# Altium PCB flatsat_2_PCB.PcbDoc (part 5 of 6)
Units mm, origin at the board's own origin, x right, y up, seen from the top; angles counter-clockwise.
Board outline 400 x 250 mm, 4 copper layers (Top Layer, FlatSat GND, FlatSat VCC, Bottom Layer), stack 2.102 mm thick; 196 components, 289 nets, 1724 pads, 1139 vias.
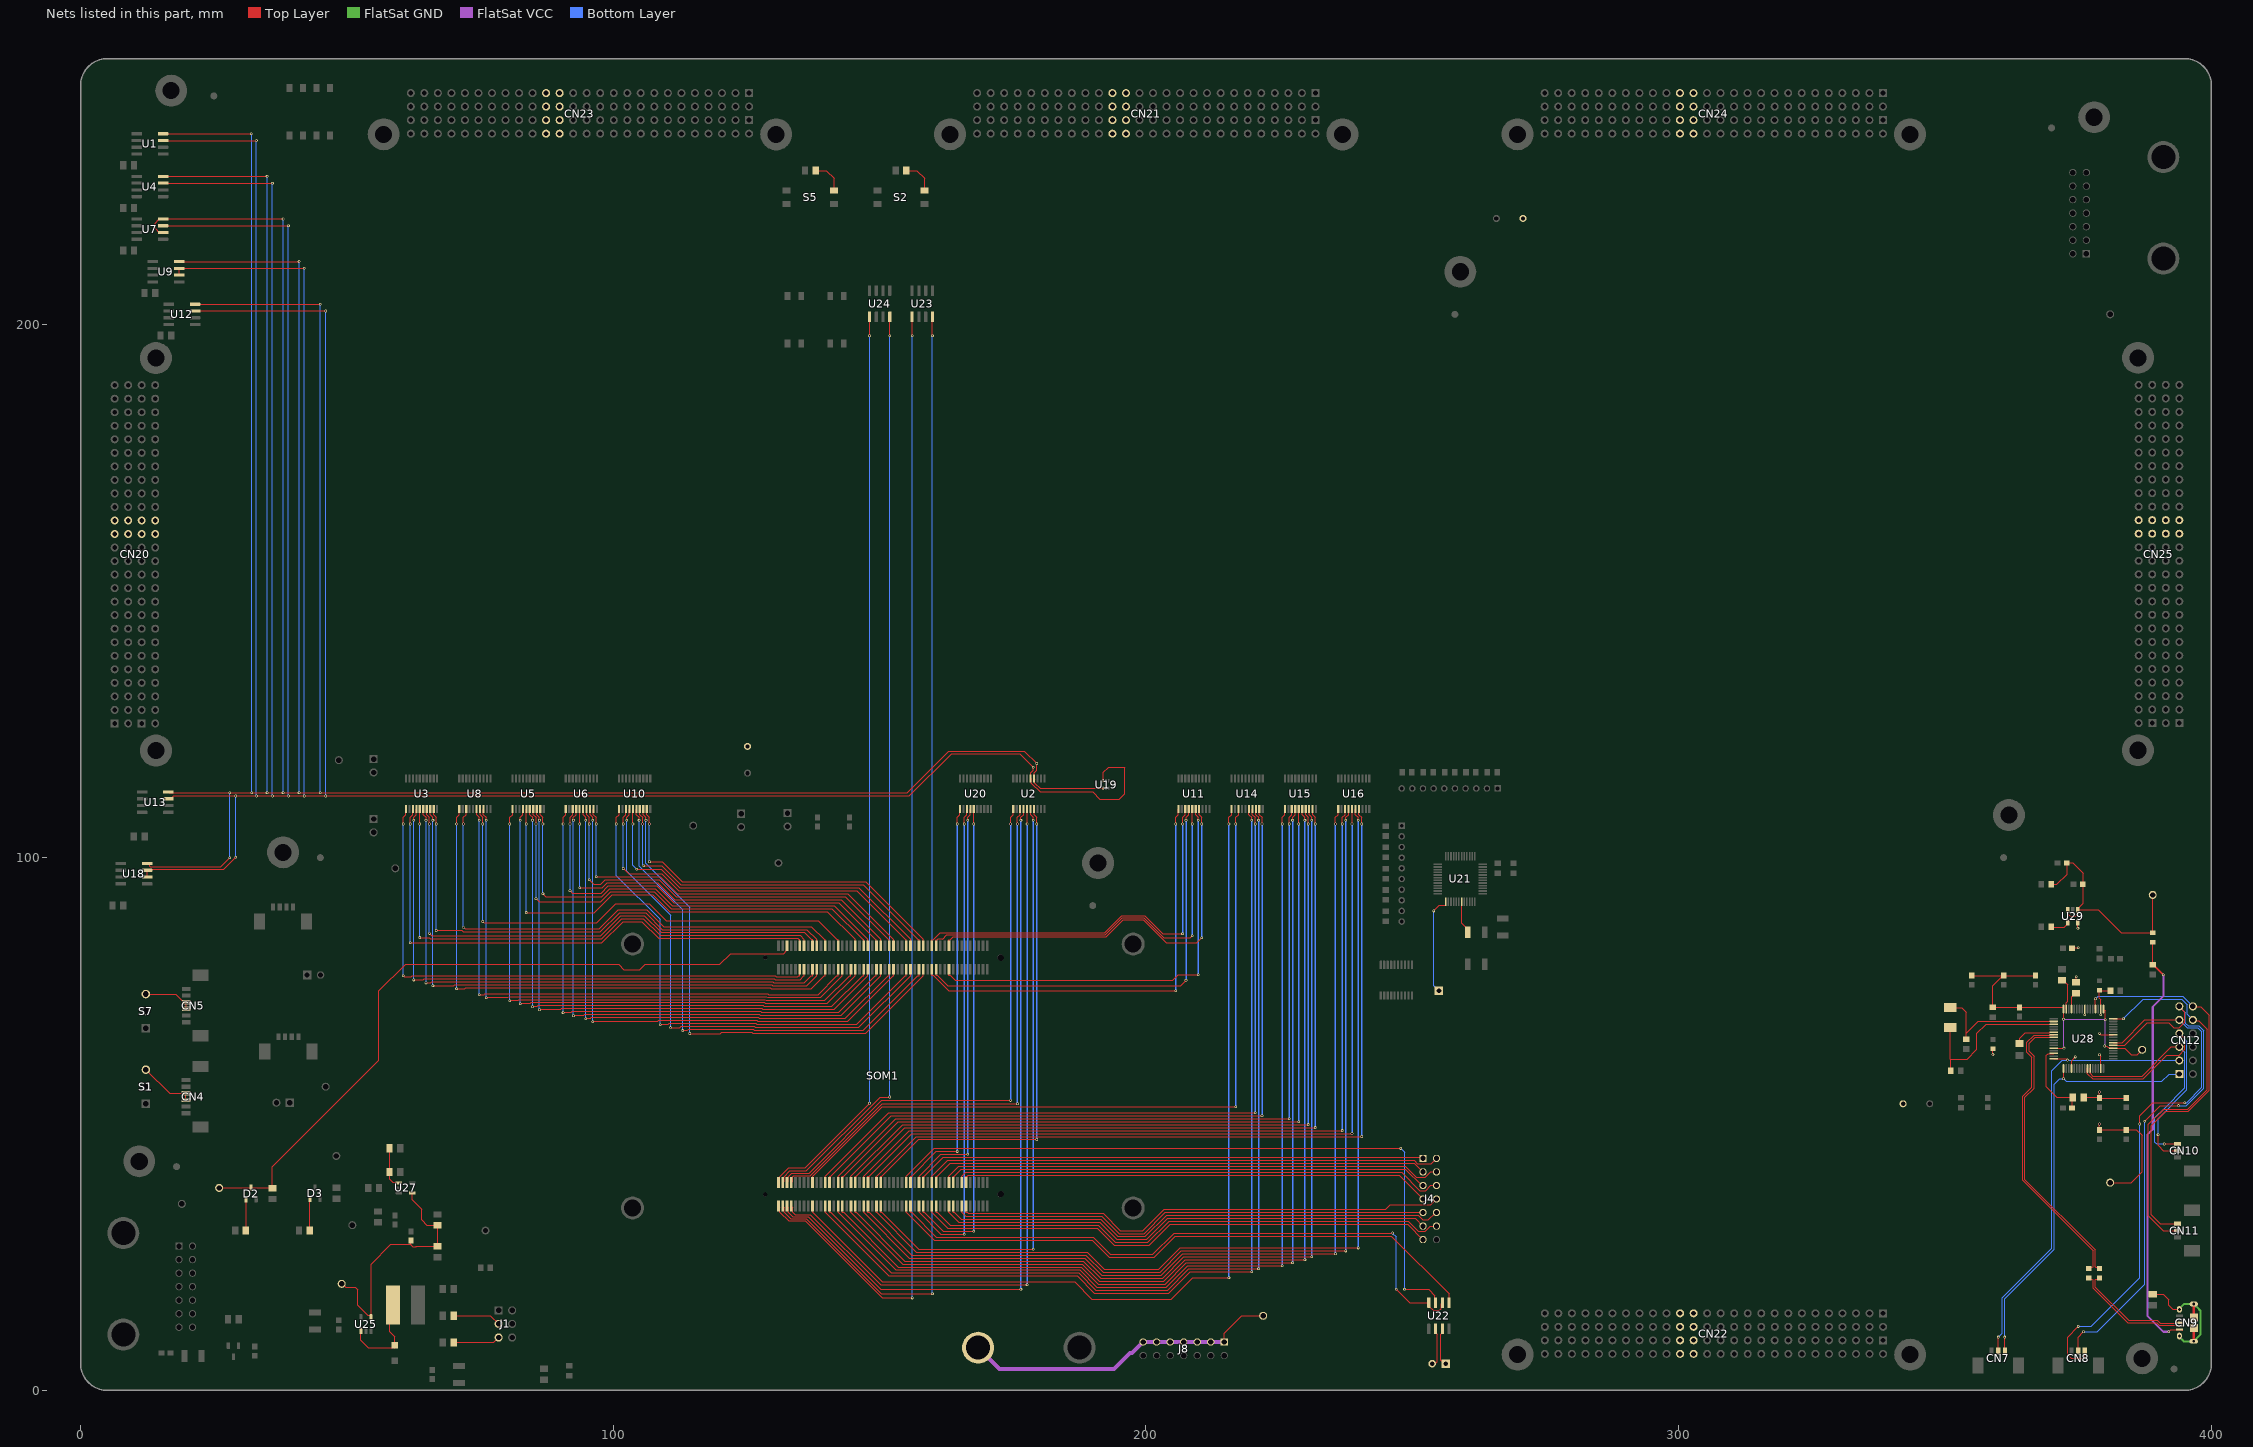
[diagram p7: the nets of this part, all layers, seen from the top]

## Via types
v1: diameter 0.508, hole 0.3, Top Layer to Bottom Layer, tented both sides, 1073 vias
v2: diameter 0.762, hole 0.45, Top Layer to Bottom Layer, tented both sides, 66 vias

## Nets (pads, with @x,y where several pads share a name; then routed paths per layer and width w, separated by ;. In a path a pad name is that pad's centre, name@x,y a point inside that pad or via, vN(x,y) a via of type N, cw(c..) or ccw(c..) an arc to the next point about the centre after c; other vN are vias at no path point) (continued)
NetC18_1: C18.1 U21.43 | length 6.2
  Top Layer w0.203: U21.43@259.25,91.75 259.25,87.7 260.4,86.55 C18.1@260.4,86
NetC31_1: C31.1 CN9.1 FB2.1 | length 80.2
  Top Layer w0.203: C31.1@389,79.925 FB2.1@389,84.111 ; v1(392,11) 392.4,11.4 CN9.1@394,11.4 394.475,11.4 CN9.1@394.573,11.302
  Top Layer w0.381: C31.1@389,79.925 389.075,79.925 v1(391,78)
  FlatSat VCC w0.381: v1(391,78) 391,74 389,72 389,49 388,48 388,14 391,11 v1(392,11)
NetC39_1: C39.1 R22.1 U28.14 | length 15.3
  Top Layer w0.203: U28.14@370.425,63.25 370.406,63.231 369.351,63.231 369,62.881 369,57 371,55 R22.1@373.984,55 373.85,54.866 C39.1@373.85,53
NetC40_2: C40.2 U28.2 XTAL1.1 | length 25.8
  Top Layer w0.203: XTAL1.1@351,71.85 353.15,71.85 354,71 354,67 ; C40.2@354,65.925 354,67 ; U28.2@370.425,69.25 356.25,69.25 354,67
NetC41_2: C41.2 U28.3 XTAL1.2 | length 32.1
  Top Layer w0.203: XTAL1.2@351,68.15 351,62.15 ; C41.2@351.075,60 351.075,62.075 351,62.15 ; U28.3@370.425,68.75 357.75,68.75 356,67 356,64 354.15,62.15 351,62.15
NetC48_1: C48.1 U29.4 | length 3.7
  Top Layer w0.203: C48.1@369.925,87 370.025,86.9 372.375,86.9 373.05,87.575 U29.4@373.05,87.8
NetCN14_1: CN14.1 U21.37 | length 18.8
  Top Layer w0.203: v1(254,90) 255.052,91.052 256.202,91.052 256.25,91.1 U21.37@256.25,91.75
  Bottom Layer w0.203: v1(254,90) 254,76 CN14.1@255,75
NetD1_1: D1.1 L1.1 U25.1 | length 17.7
  Top Layer w0.203: U25.1@52.612,11.185 52.612,9.388 54,8 58.525,8 D1.1@58.945,8.42 ; L1.1@58.65,16 58,15.35 58,11 58.945,10.055 D1.1@58.945,8.42 ; D1.1@58.895,8 58.945,7.95 D1.1@58.945,8.42 ; D1.1@59,8.475 D1.1@58.945,8.42
NetD2_1: D2.1 R2.1 | length 5.9
  Top Layer w0.203: R2.1@31.016,30 31.05,30.034 D2.1@31.05,35.89
NetD3_1: D3.1 R7.1 | length 6
  Top Layer w0.203: R7.1@43.016,30 43.05,30.034 D3.1@43.05,35.945
NetJ1_3: J1.3 R4.1 | length 9.1
  Top Layer w0.203: R4.1@70.016,14 76.92,14 J1.3@78.46,12.46
NetJ1_5: J1.5 R5.1 | length 8.8
  Top Layer w0.203: R5.1@70.016,9 77.54,9 J1.5@78.46,9.92
NetR12_1: R12.1 R15.2 U27.1 | length 7.8
  Top Layer w0.203: R12.1@57.984,45.44 R15.2@57.984,41 58,40.984 58,39.64 58.59,39.05 59.645,39.05 U27.1@59.745,38.95
NetR16_2: R16.2 S2.1B | length 6.3
  Top Layer w0.203: R16.2@155.016,229 157,229 158.45,227.55 S2.1B@158.45,225.27
NetR17_2: R17.2 S5.1B | length 6.3
  Top Layer w0.203: R17.2@138.016,229 140,229 141.45,227.55 S5.1B@141.45,225.27
NetR19_2: R19.2 U28.6 | length 7.9
  Top Layer w0.203: R19.2@364,65.143 364,66.1 365.067,67.167 369.641,67.167 369.724,67.25 U28.6@370.425,67.25
NetR23_1: R23.1 U28.63 | length 6
  Top Layer w0.203: R23.1@372,76.984 372.162,76.984 373,76.146 373,73.006 372.75,72.756 U28.63@372.75,71.575
NetR24_1: R24.1 U28.61 | length 3.4
  Top Layer w0.203: U28.61@373.75,71.575 373.75,73.846 374.457,74.553 R24.1@374.619,74.553
NO_KILL_SWITCH_1: CN4.3 CN4.4 S1.3 | length 10.6
  Top Layer w0.203: S1.3@12.245,60.2 16.679,55.766 CN4.4@19.774,55.766 CN4.3@19.774,54.516
NO_KILL_SWITCH_2: CN5.3 CN5.4 S7.3 | length 9.5
  Top Layer w0.203: S7.3@12.239,74.4 17.846,74.4 19.38,72.866 CN5.4@19.78,72.866 CN5.3@19.78,71.616 CN5.3@19.755,71.641
P1: SOM1.JX1-12 U3.1 | length 107.4
  Top Layer w0.203: v1(60.568,106.321) 60.568,107.579 61.075,108.087 U3.1@61.075,109.13 ; v1@60.602,77.843 60.78,77.666 62.108,77.666 62.286,77.844 130.415,77.844 130.593,77.666 134.607,77.666 134.785,77.844 135,77.844 SOM1.JX1-12@135,79.05
  Top Layer w0.381: v1(60.568,77.843) v1@60.602,77.843
  Bottom Layer w0.203: v1(60.568,77.843) v1(60.568,106.321)
P2: SOM1.JX1-11 U3.3 | length 102.7
  Top Layer w0.203: v1(61.868,84) 85.746,84 97.852,84 101.858,88.007 105.362,88.007 108.534,84.835 134.607,84.835 134.785,84.657 135,84.657 SOM1.JX1-11@135,83.45 ; v1(61.868,106.321) 61.868,107.579 62.375,108.087 U3.3@62.375,109.13
  Bottom Layer w0.203: v1(61.868,84) v1(61.868,106.321)
P3: SOM1.JX1-14 U3.4 | length 107.3
  Top Layer w0.203: v1(62.518,77.043) 64.27,77.043 64.511,77.285 130.184,77.285 130.362,77.107 135.054,77.107 135.791,77.844 135.8,77.844 SOM1.JX1-14@135.8,79.05 ; v1(62.518,107.006) 62.518,107.579 63.025,108.087 U3.4@63.025,109.13
  Bottom Layer w0.203: v1(62.518,77.043) v1(62.518,107.006)
P4: SOM1.JX1-13 U3.5 | length 100.7
  Top Layer w0.203: v1(63.675,85) 65.466,85 65.663,84.803 97.864,84.803 101.627,88.566 105.593,88.566 108.765,85.394 135.054,85.394 135.791,84.657 135.8,84.657 SOM1.JX1-13@135.8,83.45 ; v1(63.675,106.321) U3.5@63.675,109.13
  Bottom Layer w0.203: v1(63.675,85) v1(63.675,106.321)
P5: SOM1.JX1-18 U3.6 | length 107.3
  Top Layer w0.203: U3.6@64.325,109.13 64.325,108.087 64.832,107.579 v1(64.832,107.006) ; v1@64.857,76.508 65.684,76.508 65.901,76.726 129.952,76.726 130.13,76.547 135.889,76.547 137.185,77.844 137.4,77.844 SOM1.JX1-18@137.4,79.05
  Top Layer w0.381: v1(64.832,76.484) v1@64.857,76.508
  Bottom Layer w0.203: v1(64.832,76.484) v1(64.832,107.006)
P6: SOM1.JX1-17 U3.7 | length 100.3
  Top Layer w0.203: U3.7@64.975,109.13 64.975,108.087 65.482,107.579 v1(65.482,106.321) ; v1(65.482,85.774) 65.895,85.362 97.633,85.362 101.395,89.125 105.825,89.125 108.997,85.953 135.889,85.953 137.185,84.657 137.4,84.657 SOM1.JX1-17@137.4,83.45
  Bottom Layer w0.203: v1(65.482,85.774) v1(65.482,106.321)
P7: SOM1.JX1-20 U3.8 | length 107.6
  Top Layer w0.203: U3.8@65.625,109.13 65.625,108.087 66.132,107.579 v1(66.132,107.006) ; v1(66.132,75.939) 70.018,75.939 70.246,76.166 129.721,76.166 129.899,75.988 136.336,75.988 138.191,77.844 138.2,77.844 SOM1.JX1-20@138.2,79.05
  Bottom Layer w0.203: v1(66.132,75.939) v1(66.132,107.006)
P8: SOM1.JX1-19 U3.9 | length 99.3
  Top Layer w0.203: U3.9@66.275,109.13 66.275,108.087 66.782,107.579 v1(66.782,106.321) ; v1(66.782,86.334) 71.546,86.334 71.807,86.073 97.553,86.073 101.164,89.684 106.056,89.684 109.229,86.512 136.336,86.512 138.191,84.657 138.2,84.657 SOM1.JX1-19@138.2,83.45
  Bottom Layer w0.203: v1(66.782,86.334) v1(66.782,106.321)
P9: SOM1.JX1-24 U8.1 | length 105.6
  Top Layer w0.203: v1(70.568,106.321) 70.568,107.579 71.075,108.087 U8.1@71.075,109.13 ; v1@70.602,75.366 70.665,75.429 72.108,75.429 72.286,75.607 129.489,75.607 129.667,75.429 137.171,75.429 139.585,77.844 139.8,77.844 SOM1.JX1-24@139.8,79.05
  Top Layer w0.381: v1(70.568,75.366) v1@70.602,75.366
  Bottom Layer w0.203: v1(70.568,75.366) v1(70.568,106.321)
P10: SOM1.JX1-23 U8.3 | length 95.5
  Top Layer w0.203: v1(71.868,106.321) 71.868,107.579 72.375,108.087 U8.3@72.375,109.13 ; v1@71.894,86.893 72.154,86.632 97.321,86.632 100.932,90.243 106.288,90.243 109.46,87.071 137.171,87.071 139.585,84.657 139.8,84.657 SOM1.JX1-23@139.8,83.45
  Top Layer w0.381: v1(71.868,86.893) v1@71.894,86.893
  Bottom Layer w0.203: v1(71.868,86.893) v1(71.868,106.321)
P11: SOM1.JX1-30 U8.6 | length 105.3
  Top Layer w0.203: U8.6@74.325,109.13 74.325,108.087 74.832,107.579 v1(74.832,107.006) ; v1@74.867,74.248 74.93,74.311 75.723,74.311 75.901,74.489 129.026,74.489 129.204,74.311 138.453,74.311 141.985,77.844 142.2,77.844 SOM1.JX1-30@142.2,79.05
  Top Layer w0.381: v1(74.832,74.248) v1@74.867,74.248
  Bottom Layer w0.203: v1(74.832,74.248) v1(74.832,107.006)
P12: SOM1.JX1-29 U8.7 | length 93.6
  Top Layer w0.203: U8.7@74.975,109.13 74.975,108.087 75.482,107.579 v1(75.482,106.321) ; v1@75.515,88.011 75.769,87.756 96.864,87.756 100.469,91.361 106.751,91.361 109.923,88.189 138.453,88.189 141.985,84.657 142.2,84.657 SOM1.JX1-29@142.2,83.45
  Top Layer w0.381: v1(75.482,88.011) v1@75.515,88.011
  Bottom Layer w0.203: v1(75.482,88.011) v1(75.482,106.321)
P13: SOM1.JX1-32 U8.8 | length 105.6
  Top Layer w0.203: U8.8@75.625,109.13 75.625,108.087 76.132,107.579 v1(76.132,107.006) ; v1@76.167,73.689 76.23,73.752 80.158,73.752 80.336,73.93 128.795,73.93 128.973,73.752 138.9,73.752 142.991,77.844 143,77.844 SOM1.JX1-32@143,79.05
  Top Layer w0.381: v1(76.132,73.689) v1@76.167,73.689
  Bottom Layer w0.203: v1(76.132,73.689) v1(76.132,107.006)
P14: SOM1.JX1-36 U5.1 | length 103.5
  Top Layer w0.203: v1(80.568,106.321) 80.568,107.579 81.075,108.087 U5.1@81.075,109.13 ; v1@80.602,73.13 80.665,73.193 82.108,73.193 82.286,73.371 128.563,73.371 128.741,73.193 139.735,73.193 144.385,77.844 144.6,77.844 SOM1.JX1-36@144.6,79.05
  Top Layer w0.381: v1(80.568,73.13) v1@80.602,73.13
  Bottom Layer w0.203: v1(80.568,73.13) v1(80.568,106.321)
P15: SOM1.JX1-38 U5.4 | length 103.2
  Top Layer w0.203: v1(82.518,107.006) 82.518,107.579 83.025,108.087 U5.4@83.025,109.13 ; v1@82.552,72.571 82.615,72.634 84.423,72.634 84.601,72.812 128.331,72.812 128.509,72.634 140.182,72.634 145.391,77.844 145.4,77.844 SOM1.JX1-38@145.4,79.05
  Top Layer w0.381: v1(82.518,72.571) v1@82.552,72.571
  Bottom Layer w0.203: v1(82.518,72.571) v1(82.518,107.006)
P16: SOM1.JX1-37 U5.5 | length 87.2
  Top Layer w0.203: v1(83.675,89.688) 96.424,89.688 99.774,93.038 107.446,93.038 110.618,89.866 140.182,89.866 145.391,84.657 145.4,84.657 SOM1.JX1-37@145.4,83.45 ; v1(83.675,106.321) U5.5@83.675,109.13
  Bottom Layer w0.203: v1(83.675,89.688) v1(83.675,106.321)
P17: SOM1.JX1-42 U5.6 | length 103.3
  Top Layer w0.203: U5.6@84.325,109.13 84.325,108.087 84.832,107.579 v1(84.832,107.006) ; v1@84.867,72.012 84.93,72.075 85.723,72.075 85.901,72.253 128.1,72.253 128.278,72.075 141.017,72.075 146.785,77.844 147,77.844 SOM1.JX1-42@147,79.05
  Top Layer w0.381: v1(84.832,72.012) v1@84.867,72.012
  Bottom Layer w0.203: v1(84.832,72.012) v1(84.832,107.006)
P18: SOM1.JX1-41 U5.7 | length 84.5
  Top Layer w0.203: U5.7@84.975,109.13 84.975,108.087 85.482,107.579 v1(85.482,106.321) ; v1(85.482,92.312) 86.061,91.733 97.679,91.733 99.543,93.597 107.677,93.597 110.849,90.425 141.017,90.425 146.785,84.657 147,84.657 SOM1.JX1-41@147,83.45
  Bottom Layer w0.203: v1(85.482,92.312) v1(85.482,106.321)
P19: SOM1.JX1-44 U5.8 | length 103.6
  Top Layer w0.203: U5.8@85.625,109.13 85.625,108.087 86.132,107.579 v1(86.132,107.006) ; v1@86.167,71.453 86.23,71.516 90.158,71.516 90.336,71.694 127.868,71.694 128.046,71.516 141.464,71.516 147.791,77.844 147.8,77.844 SOM1.JX1-44@147.8,79.05
  Top Layer w0.381: v1(86.132,71.453) v1@86.167,71.453
  Bottom Layer w0.203: v1(86.132,71.453) v1(86.132,107.006)
P20: SOM1.JX1-43 U5.9 | length 83.1
  Top Layer w0.203: U5.9@86.275,109.13 86.275,108.087 86.782,107.579 v1(86.782,106.321) ; v1(86.782,93.207) 87.335,92.654 97.81,92.654 99.311,94.156 107.909,94.156 111.081,90.984 141.464,90.984 147.791,84.657 147.8,84.657 SOM1.JX1-43@147.8,83.45
  Bottom Layer w0.203: v1(86.782,93.207) v1(86.782,106.321)
P21: SOM1.JX1-48 U6.1 | length 101.5
  Top Layer w0.203: v1(90.568,106.321) 90.568,107.579 91.075,108.087 U6.1@91.075,109.13 ; v1@90.602,70.894 90.665,70.957 92.108,70.957 92.286,71.135 127.637,71.135 127.815,70.957 142.299,70.957 149.185,77.844 149.4,77.844 SOM1.JX1-48@149.4,79.05
  Top Layer w0.381: v1(90.568,70.894) v1@90.602,70.894
  Bottom Layer w0.203: v1(90.568,70.894) v1(90.568,106.321)
P22: SOM1.JX1-47 U6.3 | length 79.2
  Top Layer w0.203: v1(91.868,93.766) 92.278,93.355 97.72,93.355 99.08,94.715 108.14,94.715 111.312,91.543 142.299,91.543 149.185,84.657 149.4,84.657 SOM1.JX1-47@149.4,83.45 ; v1(91.868,106.321) 91.868,107.579 92.375,108.087 U6.3@92.375,109.13
  Bottom Layer w0.203: v1(91.868,93.766) v1(91.868,106.321)
P23: SOM1.JX1-50 U6.4 | length 101.2
  Top Layer w0.203: v1(92.518,107.006) 92.518,107.579 93.025,108.087 U6.4@93.025,109.13 ; v1@92.552,70.335 92.615,70.398 94.423,70.398 94.601,70.576 127.405,70.576 127.583,70.398 142.745,70.398 150.191,77.844 150.2,77.844 SOM1.JX1-50@150.2,79.05
  Top Layer w0.381: v1(92.518,70.335) v1@92.552,70.335
  Bottom Layer w0.203: v1(92.518,70.335) v1(92.518,107.006)
P24: SOM1.JX1-49 U6.5 | length 77.3
  Top Layer w0.203: v1(93.675,94.325) 97.899,94.325 98.848,95.274 108.372,95.274 111.544,92.102 142.746,92.102 150.191,84.657 150.2,84.657 SOM1.JX1-49@150.2,83.45 ; v1(93.675,106.321) U6.5@93.675,109.13
  Bottom Layer w0.203: v1(93.675,94.325) v1(93.675,106.321)
P25: SOM1.JX1-54 U6.6 | length 101.2
  Top Layer w0.203: U6.6@94.325,109.13 94.325,108.087 94.832,107.579 v1(94.832,107.006) ; v1@94.867,69.776 94.93,69.839 95.723,69.839 95.901,70.017 127.174,70.017 127.352,69.839 143.581,69.839 151.585,77.844 151.8,77.844 SOM1.JX1-54@151.8,79.05
  Top Layer w0.381: v1(94.832,69.776) v1@94.867,69.776
  Bottom Layer w0.203: v1(94.832,69.776) v1(94.832,107.006)
P26: SOM1.JX1-53 U6.7 | length 76.4
  Top Layer w0.203: U6.7@94.975,109.13 94.975,108.087 95.482,107.579 v1(95.482,106.321) ; v1(95.482,95.833) 96.315,95 97.683,95 98.516,95.833 108.603,95.833 111.776,92.661 143.581,92.661 151.585,84.657 151.8,84.657 SOM1.JX1-53@151.8,83.45
  Bottom Layer w0.203: v1(95.482,95.833) v1(95.482,106.321)
P27: SOM1.JX1-56 U6.8 | length 101.5
  Top Layer w0.203: U6.8@95.625,109.13 95.625,108.087 96.132,107.579 v1(96.132,107.006) ; v1@96.167,69.217 96.23,69.28 108.376,69.28 108.554,69.458 126.942,69.458 127.12,69.28 144.027,69.28 152.591,77.844 152.6,77.844 SOM1.JX1-56@152.6,79.05
  Top Layer w0.381: v1(96.132,69.217) v1@96.167,69.217
  Bottom Layer w0.203: v1(96.132,69.217) v1(96.132,107.006)
P28: SOM1.JX1-55 U6.9 | length 74.8
  Top Layer w0.203: U6.9@96.275,109.13 96.275,108.087 96.782,107.579 v1(96.782,106.321) ; v1(96.782,96.392) 108.835,96.392 112.007,93.22 144.028,93.22 152.591,84.657 152.6,84.657 SOM1.JX1-55@152.6,83.45
  Bottom Layer w0.203: v1(96.782,96.392) v1(96.782,106.321)
P29: SOM1.JX1-62 U10.1 | length 95.5
  Top Layer w0.203: v1(100.568,106.321) 100.568,107.579 101.075,108.087 U10.1@101.075,109.13 ; v1@108.819,68.658 108.883,68.721 110.326,68.721 110.504,68.899 126.711,68.899 126.889,68.721 145.663,68.721 154.785,77.844 155,77.844 SOM1.JX1-62@155,79.05
  Top Layer w0.381: v1(108.785,68.658) v1@108.819,68.658
  Bottom Layer w0.203: v1(100.568,106.321) 100.568,96.643 108.785,88.426 v1(108.785,68.658)
P30: SOM1.JX1-61 U10.3 | length 71.2
  Top Layer w0.203: v1(101.868,97.969) 102.886,96.951 109.067,96.951 112.239,93.779 145.663,93.779 154.785,84.657 155,84.657 SOM1.JX1-61@155,83.45 ; v1(101.868,106.321) 101.868,107.579 102.375,108.087 U10.3@102.375,109.13
  Bottom Layer w0.203: v1(101.868,97.969) v1(101.868,106.321)
P31: SOM1.JX1-64 U10.4 | length 95.1
  Top Layer w0.203: v1(102.518,107.006) 102.518,107.579 103.025,108.087 U10.4@103.025,109.13 ; v1(110.735,68.099) 112.487,68.099 112.729,68.34 126.479,68.34 126.657,68.162 146.109,68.162 155.79,77.844 155.8,77.844 SOM1.JX1-64@155.8,79.05
  Bottom Layer w0.203: v1(102.518,107.006) 102.518,97.451 110.735,89.233 v1(110.735,68.099)
P32: SOM1.JX1-63 U10.5 | length 69.7
  Top Layer w0.203: v1(103.675,106.321) U10.5@103.675,109.13 ; v1(104.397,97.811) 108.997,97.811 112.47,94.338 146.11,94.338 155.791,84.657 155.8,84.657 SOM1.JX1-63@155.8,83.45
  Bottom Layer w0.203: v1(103.675,106.321) 103.675,98.532 v1(104.397,97.811)
P33: SOM1.JX1-68 U10.6 | length 95.2
  Top Layer w0.203: U10.6@104.325,109.13 104.325,108.087 104.832,107.579 v1(104.832,107.006) ; v1@113.074,67.564 113.901,67.564 114.118,67.781 126.248,67.781 126.426,67.603 146.945,67.603 157.185,77.844 157.4,77.844 SOM1.JX1-68@157.4,79.05
  Top Layer w0.381: v1(113.05,67.54) v1@113.074,67.564
  Bottom Layer w0.203: v1(104.832,107.006) 104.832,98.41 113.05,90.192 v1(113.05,67.54)
P34: SOM1.JX1-70 U10.8 | length 95.5
  Top Layer w0.203: U10.8@105.625,109.13 105.625,108.087 106.132,107.579 v1(106.132,107.006) ; v1(114.35,66.981) 120.079,66.981 120.321,67.222 126.016,67.222 126.194,67.044 147.391,67.044 158.19,77.844 158.2,77.844 SOM1.JX1-70@158.2,79.05
  Bottom Layer w0.203: v1(106.132,107.006) 106.132,98.948 114.35,90.731 v1(114.35,66.981)
P35: SOM1.JX1-69 U10.9 | length 68.8
  Top Layer w0.203: U10.9@106.275,109.13 106.275,108.087 106.782,107.579 v1(106.782,106.321) ; v1@106.773,99.214 109.175,99.214 112.933,95.456 147.392,95.456 158.191,84.657 158.2,84.657 SOM1.JX1-69@158.2,83.45
  Bottom Layer w0.203: v1@106.782,99.218 v1(106.782,106.321)
  other v1: 106.786,99.214
P36: SOM1.JX1-74 U11.1 | length 82.4
  Top Layer w0.203: SOM1.JX1-74@159.8,79.05 159.8,77.932 160.052,77.932 162.985,75 v1(205.568,75) ; v1(205.568,106.321) 205.568,107.579 206.075,108.087 U11.1@206.075,109.13
  Bottom Layer w0.279: v1(205.568,75) v1(205.568,106.321)
P37: SOM1.JX1-76 U11.4 | length 81.6
  Top Layer w0.203: SOM1.JX1-76@160.6,79.05 160.6,77.932 160.852,77.932 162.785,76 206.518,76 v1(207.518,77) ; v1(207.518,107.006) 207.518,107.579 208.025,108.087 U11.4@208.025,109.13
  Bottom Layer w0.279: v1(207.518,77) v1(207.518,107.006)
P38: SOM1.JX1-75 U11.5 | length 76.4
  Top Layer w0.203: SOM1.JX1-75@160.6,83.45 160.6,84.568 160.852,84.568 161.03,84.746 161.77,84.746 161.8,84.715 162.593,85.508 192.387,85.508 195.559,88.68 199.621,88.68 203.301,85 208.345,85 v1(208.675,85.33) ; v1(208.675,106.321) U11.5@208.675,109.13
  Bottom Layer w0.279: v1(208.675,85.33) v1(208.675,106.321)
P39: SOM1.JX1-82 U11.6 | length 80.1
  Top Layer w0.203: SOM1.JX1-82@163,79.05 163,77.932 163.252,77.932 164.185,77 205,77 206.03,78.03 v1(209.832,78.03) ; U11.6@209.325,109.13 209.325,108.087 209.832,107.579 v1(209.832,107.006)
  Bottom Layer w0.279: v1(209.832,78.03) 209.832,78.363 v1(209.832,107.006)
P40: SOM1.JX1-81 U11.7 | length 76.7
  Top Layer w0.203: SOM1.JX1-81@163,83.45 163,84.568 163.252,84.568 163.811,85.127 192.545,85.127 195.717,88.299 199.463,88.299 203.762,84 209.534,84 v1(210.482,84.949) ; U11.7@209.975,109.13 209.975,108.087 210.482,107.579 v1(210.482,106.321)
  Bottom Layer w0.279: v1(210.482,84.949) v1(210.482,106.321)
P41: SOM1.JX2-18 U14.1 | length 176
  Top Layer w0.203: SOM1.JX2-18@137.4,34.6 137.4,33.394 137.409,33.394 150.444,20.358 186.642,20.358 189.857,17.143 204.744,17.143 208.744,21.143 v1(215.568,21.143) ; v1(215.568,106.321) 215.568,107.579 216.075,108.087 U14.1@216.075,109.13
  Bottom Layer w0.279: v1(215.568,21.143) v1(215.568,106.321)
P42: SOM1.JX2-17 U14.3 | length 142.2
  Top Layer w0.203: SOM1.JX2-17@137.4,39 137.4,40.207 137.409,40.207 150.444,53.242 v1(216.868,53.242) ; v1(216.868,106.321) 216.868,107.579 217.375,108.087 U14.3@217.375,109.13
  Bottom Layer w0.279: v1(216.868,53.242) v1(216.868,106.321)
P43: SOM1.JX2-24 U14.6 | length 176.2
  Top Layer w0.203: SOM1.JX2-24@139.8,34.6 139.8,33.394 139.809,33.394 151.726,21.476 187.105,21.476 190.32,18.261 204.281,18.261 208.281,22.261 v1(219.832,22.261) ; U14.6@219.325,109.13 219.325,108.087 219.832,107.579 v1(219.832,107.006)
  Bottom Layer w0.279: v1(219.832,22.261) v1(219.832,107.006)
P44: SOM1.JX2-23 U14.7 | length 144
  Top Layer w0.203: SOM1.JX2-23@139.8,39 139.8,40.207 139.809,40.207 151.726,52.124 v1(220.482,52.124) ; U14.7@219.975,109.13 219.975,108.087 220.482,107.579 v1(220.482,106.321)
  Bottom Layer w0.279: v1(220.482,52.124) v1(220.482,106.321)
P45: SOM1.JX2-26 U14.8 | length 176
  Top Layer w0.203: SOM1.JX2-26@140.6,34.6 140.6,33.394 140.815,33.394 152.173,22.035 187.336,22.035 190.552,18.82 204.05,18.82 208.05,22.82 v1(221.132,22.82) ; U14.8@220.625,109.13 220.625,108.087 221.132,107.579 v1(221.132,107.006)
  Bottom Layer w0.279: v1(221.132,22.82) v1(221.132,107.006)
P46: SOM1.JX2-25 U14.9 | length 144.9
  Top Layer w0.203: SOM1.JX2-25@140.6,39 140.6,40.207 140.815,40.207 152.173,51.565 v1(221.782,51.565) ; U14.9@221.275,109.13 221.275,108.087 221.782,107.579 v1(221.782,106.321)
  Bottom Layer w0.279: v1(221.782,51.565) v1(221.782,106.321)
P47: SOM1.JX2-30 U15.1 | length 178
  Top Layer w0.203: SOM1.JX2-30@142.2,34.6 142.2,33.394 142.209,33.394 153.008,22.594 187.568,22.594 190.783,19.379 203.818,19.379 207.818,23.379 v1(225.568,23.379) ; v1(225.568,106.321) 225.568,107.579 226.075,108.087 U15.1@226.075,109.13
  Bottom Layer w0.279: v1(225.568,23.379) v1(225.568,106.321)
P48: SOM1.JX2-29 U15.3 | length 148.7
  Top Layer w0.203: SOM1.JX2-29@142.2,39 142.2,40.207 142.209,40.207 153.008,51.006 v1(226.868,51.006) ; v1(226.868,106.321) 226.868,107.579 227.375,108.087 U15.3@227.375,109.13
  Bottom Layer w0.279: v1(226.868,51.006) v1(226.868,106.321)
P49: SOM1.JX2-31 U15.5 | length 149.8
  Top Layer w0.203: SOM1.JX2-31@143,39 143,40.207 143.215,40.207 153.455,50.447 v1(228.675,50.447) ; v1(228.675,106.321) U15.5@228.675,109.13
  Bottom Layer w0.279: v1(228.675,50.447) v1(228.675,106.321)
P50: SOM1.JX2-36 U15.6 | length 178.3
  Top Layer w0.203: SOM1.JX2-36@144.6,34.6 144.6,33.394 144.609,33.394 154.29,23.712 188.031,23.712 191.246,20.497 203.355,20.497 207.355,24.497 v1(229.832,24.497) ; U15.6@229.325,109.13 229.325,108.087 229.832,107.579 v1(229.832,107.006)
  Bottom Layer w0.279: v1(229.832,24.497) v1(229.832,107.006)
P51: SOM1.JX2-35 U15.7 | length 150.6
  Top Layer w0.203: SOM1.JX2-35@144.6,39 144.6,40.207 144.609,40.207 154.29,49.888 v1(230.482,49.888) ; U15.7@229.975,109.13 229.975,108.087 230.482,107.579 v1(230.482,106.321)
  Bottom Layer w0.279: v1(230.482,49.888) v1(230.482,106.321)
P52: SOM1.JX2-37 U15.9 | length 151.4
  Top Layer w0.203: SOM1.JX2-37@145.4,39 145.4,40.207 145.615,40.207 154.737,49.329 v1(231.782,49.329) ; U15.9@231.275,109.13 231.275,108.087 231.782,107.579 v1(231.782,106.321)
  Bottom Layer w0.279: v1(231.782,49.329) v1(231.782,106.321)
P53: SOM1.JX2-42 U16.1 | length 180
  Top Layer w0.203: SOM1.JX2-42@147,34.6 147,33.394 147.009,33.394 155.572,24.83 188.494,24.83 191.709,21.615 202.892,21.615 206.892,25.615 v1(235.568,25.615) ; v1(235.568,106.321) 235.568,107.579 236.075,108.087 U16.1@236.075,109.13
  Bottom Layer w0.279: v1(235.568,25.615) v1(235.568,106.321)
P54: SOM1.JX2-41 U16.3 | length 155.2
  Top Layer w0.203: SOM1.JX2-41@147,39 147,40.207 147.009,40.207 155.572,48.77 v1(236.868,48.77) ; v1(236.868,106.321) 236.868,107.579 237.375,108.087 U16.3@237.375,109.13
  Bottom Layer w0.279: v1(236.868,48.77) v1(236.868,106.321)
P55: SOM1.JX2-44 U16.4 | length 180.4
  Top Layer w0.203: SOM1.JX2-44@147.8,34.6 147.8,33.394 148.015,33.394 156.019,25.389 188.725,25.389 191.941,22.174 202.661,22.174 206.661,26.174 v1(237.518,26.174) ; v1(237.518,107.006) 237.518,107.579 238.025,108.087 U16.4@238.025,109.13
  Bottom Layer w0.279: v1(237.518,26.174) v1(237.518,107.006)
P56: SOM1.JX2-43 U16.5 | length 156.3
  Top Layer w0.203: SOM1.JX2-43@147.8,39 147.8,40.207 148.015,40.207 156.019,48.211 v1(238.675,48.211) ; v1(238.675,106.321) U16.5@238.675,109.13
  Bottom Layer w0.279: v1(238.675,48.211) v1(238.675,106.321)
P57: SOM1.JX2-48 U16.6 | length 180.3
  Top Layer w0.203: SOM1.JX2-48@149.4,34.6 149.4,33.394 149.409,33.394 156.854,25.948 188.957,25.948 192.172,22.733 202.429,22.733 206.429,26.733 v1(239.832,26.733) ; U16.6@239.325,109.13 239.325,108.087 239.832,107.579 v1(239.832,107.006)
  Bottom Layer w0.279: v1(239.832,26.733) v1(239.832,107.006)
P58: SOM1.JX2-47 U16.7 | length 157.1
  Top Layer w0.203: SOM1.JX2-47@149.4,39 149.4,40.207 149.409,40.207 156.854,47.652 v1(240.482,47.652) ; U16.7@239.975,109.13 239.975,108.087 240.482,107.579 v1(240.482,106.321)
  Bottom Layer w0.279: v1(240.482,47.652) v1(240.482,106.321)
P59: SOM1.JX2-63 U20.1 | length 76.4
  Top Layer w0.203: SOM1.JX2-63@155.8,39 155.8,40.207 156.015,40.207 160.665,44.857 v1(164.568,44.857) ; v1(164.568,106.321) 164.568,107.579 165.075,108.087 U20.1@165.075,109.13
  Bottom Layer w0.279: v1(164.568,44.857) v1(164.568,106.321)
P60: SOM1.JX2-68 U20.3 | length 91.4
  Top Layer w0.203: SOM1.JX2-68@157.4,34.6 157.4,33.394 157.409,33.394 161.5,29.302 v1(165.868,29.302) ; v1(165.868,106.321) 165.868,107.579 166.375,108.087 U20.3@166.375,109.13
  Bottom Layer w0.279: v1(165.868,29.302) v1(165.868,106.321)
P61: SOM1.JX2-67 U20.4 | length 77.1
  Top Layer w0.203: SOM1.JX2-67@157.4,39 157.4,40.207 157.409,40.207 161.5,44.298 v1(166.518,44.298) ; v1(166.518,107.006) 166.518,107.579 167.025,108.087 U20.4@167.025,109.13
  Bottom Layer w0.279: v1(166.518,44.298) v1(166.518,107.006)
P62: SOM1.JX2-70 U20.5 | length 91.4
  Top Layer w0.203: SOM1.JX2-70@158.2,34.6 158.2,33.394 158.415,33.394 161.947,29.861 v1(167.675,29.861) ; v1(167.675,106.321) U20.5@167.675,109.13
  Bottom Layer w0.279: v1(167.675,29.861) v1(167.675,106.321)
P63: J4.1 SOM1.JX2-69 | length 96.6
  Top Layer w0.203: SOM1.JX2-69@158.2,39 158.2,40.207 158.415,40.207 161.947,43.739 251.801,43.739 J4.1@252,43.54
P64: J4.13 SOM1.JX2-74 | length 98.8
  Top Layer w0.203: SOM1.JX2-74@159.8,34.6 159.8,33.394 159.809,33.394 162.782,30.42 190.809,30.42 194.025,27.205 200.577,27.205 204.577,31.205 249.095,31.205 J4.13@252,28.3
P65: J4.2 SOM1.JX2-73 | length 97.8
  Top Layer w0.203: SOM1.JX2-73@159.8,39 159.8,40.207 159.809,40.207 162.782,43.18 250.36,43.18 250.964,42.575 253.575,42.575 J4.2@254.54,43.54
P66: J4.12 SOM1.JX2-76 | length 100.3
  Top Layer w0.203: SOM1.JX2-76@160.6,34.6 160.6,33.394 160.815,33.394 163.229,30.979 191.041,30.979 194.256,27.764 200.345,27.764 204.345,31.764 249.236,31.764 251.125,29.875 252.43,29.875 253.395,30.84 J4.12@254.54,30.84
P67: J4.3 SOM1.JX2-75 | length 94.3
  Top Layer w0.203: SOM1.JX2-75@160.6,39 160.6,40.207 160.815,40.207 163.229,42.621 250.379,42.621 J4.3@252,41
P68: J4.11 SOM1.JX2-82 | length 94.6
  Top Layer w0.203: SOM1.JX2-82@163,34.6 163,33.394 163.009,33.394 164.864,31.538 191.272,31.538 194.488,28.323 200.114,28.323 204.114,32.323 250.517,32.323 J4.11@252,30.84
P69: J4.4 SOM1.JX2-81 | length 94.8
  Top Layer w0.203: SOM1.JX2-81@163,39 163,40.207 163.009,40.207 164.864,42.062 248.687,42.062 250.713,40.035 252.467,40.035 253.432,41 J4.4@254.54,41
P70: J4.10 SOM1.JX2-84 | length 96.4
  Top Layer w0.203: SOM1.JX2-84@163.8,34.6 163.8,33.394 164.015,33.394 165.311,32.097 191.504,32.097 194.719,28.882 199.882,28.882 203.882,32.882 251.118,32.882 252,32 253,32 254.38,33.38 J4.10@254.54,33.38
P71: J4.5 SOM1.JX2-83 | length 91.2
  Top Layer w0.203: SOM1.JX2-83@163.8,39 163.8,40.207 164.015,40.207 165.311,41.503 248.707,41.503 251.749,38.46 J4.5@252,38.46
P72: J4.9 SOM1.JX2-88 | length 91.1
  Top Layer w0.203: SOM1.JX2-88@165.4,34.6 165.4,33.394 165.409,33.394 166.146,32.657 191.736,32.657 194.951,29.441 199.65,29.441 203.65,33.441 251.939,33.441 J4.9@252,33.38
P73: J4.6 SOM1.JX2-87 | length 92.5
  Top Layer w0.203: SOM1.JX2-87@165.4,39 165.4,40.207 165.409,40.207 166.146,40.944 247.976,40.944 251.424,37.495 252.495,37.495 253.46,38.46 J4.6@254.54,38.46
P74: J4.8 SOM1.JX2-90 | length 93.4
  Top Layer w0.203: SOM1.JX2-90@166.2,34.6 166.2,33.394 166.415,33.394 166.593,33.216 191.967,33.216 195.183,30 199.419,30 203.419,34 245,34 245.848,34.848 253.468,34.848 J4.8@254.54,35.92
P75: J4.7 SOM1.JX2-89 | length 88.9
  Top Layer w0.203: SOM1.JX2-89@166.2,39 166.2,40.207 166.415,40.207 166.593,40.385 247.535,40.385 J4.7@252,35.92
PC104_GND: CN20.29 CN20.30 CN20.31 CN20.32 CN20.81 CN20.82 CN20.83 CN20.84 CN21.29 CN21.30 CN21.31 CN21.32 CN21.81 CN21.82 CN21.83 CN21.84 CN22.29 CN22.30 CN22.31 CN22.32 CN22.81 CN22.82 CN22.83 CN22.84 CN23.29 CN23.30 CN23.31 CN23.32 CN23.81 CN23.82 CN23.83 CN23.84 CN24.29 CN24.30 CN24.31 CN24.32 CN24.81 CN24.82 CN24.83 CN24.84 CN25.29 CN25.30 CN25.31 CN25.32 CN25.81 CN25.82 CN25.83 CN25.84 L2.2 L3.2 L4.2
PWR_EN: D2.3 R3.2 SOM1.JX1-5 TP1.1 | length 136.8
  Top Layer w0.203: TP1.1@26,38 D2.3@32,38 35.961,38 R3.2@36,37.961 36,42 56,62 56,75 61,80 101,80 102,79 105,79 106,80 120,80 122,82 132.015,82 132.6,82.585 SOM1.JX1-5@132.6,83.45
REG_EN: C10.2 R10.1 R13.2 TP16.1 U25.4 U27.4 | length 47.9
  Top Layer w0.203: TP16.1@49,20 49.125,20 49.808,19.316 51.565,19.316 52,18.881 52,16 53.912,14.088 54.322,14.088 U25.4@54.512,13.898 ; U25.4@54.512,13.695 U25.4@54.512,13.898 ; C10.2@62,28.15 62,27.327 ; U27.4@62.255,37.05 62.255,35.745 64,34 64,32 65,31 66.984,31 R10.1@67,30.984 R13.2@67,27.016 63.016,27.016 63,27 62.327,27 62,27.327 ; U25.4@54.512,13.898 54.512,23.662 58.25,27.4 61.927,27.4 62,27.327
RS485_N: J2.2 U22.6 | length 7
  Top Layer w0.203: J2.2@253.948,5.218 254.525,5.218 254.644,5.337 254.644,10.561 254.365,10.84 U22.6@254.365,11.525
RS485_P: J2.1 U22.7 | length 7.2
  Top Layer w0.203: U22.7@255.635,11.525 255.635,10.84 255.356,10.561 255.356,5.687 255.475,5.568 255.702,5.568 J2.1@256.27,5
RX_CHN_1: SOM1.JX1-73 U11.3 | length 75.1
  Top Layer w0.203: SOM1.JX1-73@159.8,83.45 159.8,84.568 160.052,84.568 161.374,85.889 192.229,85.889 195.401,89.061 199.779,89.061 203.129,85.711 v1(206.868,85.711) ; v1(206.868,106.321) 206.868,107.579 207.375,108.087 U11.3@207.375,109.13
  Bottom Layer w0.279: v1(206.868,85.711) v1(206.868,106.321)
RX_CHN_2: SOM1.JX2-38 U15.8 | length 178
  Top Layer w0.203: SOM1.JX2-38@145.4,34.6 145.4,33.394 145.615,33.394 154.737,24.271 188.262,24.271 191.478,21.056 203.124,21.056 207.124,25.056 v1(231.132,25.056) ; U15.8@230.625,109.13 230.625,108.087 231.132,107.579 v1(231.132,107.006)
  Bottom Layer w0.279: v1(231.132,25.056) v1(231.132,107.006)
RX_CHN_3: SOM1.JX2-62 U22.1 | length 114.4
  Top Layer w0.203: SOM1.JX2-62@155,34.6 155,33.394 155.009,33.394 160.218,28.184 189.883,28.184 193.099,24.969 201.503,24.969 205.503,28.969 246.031,28.969 256.905,18.095 U22.1@256.905,16.475
RXD_CHN_1: SOM1.JX2-4 U23.4 | length 218.9
  Top Layer w0.203: SOM1.JX2-4@131.8,34.6 132.066,34.334 132.066,33.468 133.341,32.193 136.226,32.193 150.303,18.115 v1(159.905,18.115) ; v1(159.905,198) U23.4@159.905,201.53
  Bottom Layer w0.203: v1@159.905,18.095 v1(159.905,18.115) v1(159.905,198)
RXD_CHN_2: SOM1.JX2-3 U24.4 | length 173.7
  Top Layer w0.203: SOM1.JX2-3@131.8,39 132.066,39.266 132.066,40.132 133.116,41.181 136.236,41.181 150.115,55.06 v1(151.905,55.06) ; v1(151.905,198) U24.4@151.905,201.53
  Bottom Layer w0.203: v1(151.905,55.06) v1(151.905,198)
SCL_CHN_1: SOM1.JX2-7 U2.3 | length 104.6
  Top Layer w0.203: SOM1.JX2-7@133.4,39 133.666,39.266 133.666,40.132 133.83,40.296 136.95,40.296 137.242,40.588 137.252,40.588 150.467,53.803 v1(175.868,53.803) ; v1(175.868,106.321) 175.868,107.579 176.375,108.087 U2.3@176.375,109.13
  Bottom Layer w0.279: v1(175.868,53.803) v1(175.868,106.321)
SCL_CHN_2: SOM1.JX2-8 U2.5 | length 140.2
  Top Layer w0.203: SOM1.JX2-8@133.4,34.6 133.666,34.334 133.666,33.468 134.135,33 137,33 150.2,19.8 v1(177.675,19.8) ; v1(177.675,106.321) U2.5@177.675,109.13
  Bottom Layer w0.279: v1(177.675,19.8) v1(177.675,106.321)
SCL_CHN_3: SOM1.JX2-49 U2.7 | length 95.6
  Top Layer w0.203: SOM1.JX2-49@150.2,39 150.2,40.207 150.415,40.207 157.301,47.093 v1(179.482,47.093) ; U2.7@178.975,109.13 178.975,108.087 179.482,107.579 v1(179.482,106.321)
  Bottom Layer w0.279: v1(179.482,47.093) v1(179.482,106.321)
SCL_SENSORS: U1.4 U2.14 U4.4 U7.2 U7.4 U9.4 U12.4 U13.4 U18.4 U19.1 | length 861.3
  Top Layer w0.203: U18.4@12.47,98.905 12.757,98.905 12.956,98.707 12.956,98.419 13.099,98.276 26.276,98.276 v1(28,100) ; U7.2@15.47,217.365 14.785,217.365 14,218.15 14,219.12 14.785,219.905 U7.4@15.47,219.905 v1(38,219.905) ; U4.4@15.47,227.905 v1(35,227.905) ; U1.4@15.47,235.905 v1(32,235.905) ; U13.4@16.47,112.328 16.638,112.16 v1(28,112.16) v1(32.125,112.16) v1(35,112.16) v1(38,112.16) v1(41,112.16) v1(45,112.16) 155.16,112.16 163,120 177.161,120 v1(179.482,117.679) 179.482,116.421 178.975,115.913 U2.14@178.975,114.87 179.14,114.705 179.14,113.999 180.14,113 U19.1@192,113 ; U9.4@18.47,211.905 v1(41,211.905) ; U12.4@21.47,203.905 v1(45,203.905)
  Bottom Layer w0.203: v1(28,100) v1(28,112.16) ; v1(32,235.905) 32.125,235.78 v1(32.125,112.16) ; v1(35,112.16) v1(35,227.905) ; v1(38,112.16) v1(38,219.905) ; v1(41,112.16) v1(41,211.905) ; v1(45,112.16) v1(45,203.905)
SDA_CHN_1: SOM1.JX2-5 U2.1 | length 103.8
  Top Layer w0.203: SOM1.JX2-5@132.6,39 132.866,39.266 132.866,40.132 133.535,40.8 136.8,40.8 150.426,54.426 v1(174.568,54.426) ; v1(174.568,106.321) 174.568,107.579 175.075,108.087 U2.1@175.075,109.13
  Bottom Layer w0.279: v1(174.568,54.426) v1(174.568,106.321)
SDA_CHN_2: SOM1.JX2-6 U2.4 | length 141.2
  Top Layer w0.203: SOM1.JX2-6@132.6,34.6 132.866,34.334 132.866,33.468 133.72,32.615 136.585,32.615 150.2,19 v1(176.518,19) ; v1(176.518,107.006) 176.518,107.579 177.025,108.087 U2.4@177.025,109.13
  Bottom Layer w0.279: v1(176.518,19) v1(176.518,107.006)
SDA_CHN_3: SOM1.JX2-50 U2.6 | length 115.5
  Top Layer w0.203: SOM1.JX2-50@150.2,34.6 150.2,33.394 150.415,33.394 157.301,26.507 v1(178.832,26.507) ; U2.6@178.325,109.13 178.325,108.087 178.832,107.579 v1(178.832,107.006)
  Bottom Layer w0.279: v1(178.832,26.507) v1(178.832,107.006)
SDA_SENSORS: U1.3 U2.15 U4.3 U7.3 U9.2 U9.3 U12.3 U13.3 U18.2 U18.3 U19.6 | length 877
  Top Layer w0.203: U18.2@12.47,96.365 U18.3@12.47,97.635 12.638,97.803 26.873,97.803 v1(29.127,100.057) ; U7.3@15.47,218.635 v1(39,218.635) ; U4.3@15.47,226.635 v1(36,226.635) ; U1.3@15.47,234.635 v1(33,234.635) ; U13.3@16.47,111.058 17.135,111.058 17.333,111.257 17.333,111.461 17.452,111.58 v1(29.127,111.58) v1(33,111.58) v1(36,111.58) v1(39,111.58) v1(42,111.58) v1(46,111.58) 155.58,111.58 163.55,119.55 176.277,119.55 v1(178.832,116.994) 178.832,116.421 178.325,115.913 U2.15@178.325,114.87 178.49,114.705 178.49,113.999 180.14,112.35 190,112.35 191.35,111 195,111 196,112 196,116.881 195.881,117 193,117 192,116 U19.6@192,114.47 ; U9.2@18.47,209.365 U9.3@18.47,210.635 v1(42,210.635) ; U12.3@21.47,202.635 v1(46,202.635)
  Bottom Layer w0.203: v1(29.127,100.057) v1(29.127,111.58) ; v1(33,111.58) v1(33,234.635) ; v1(36,111.58) v1(36,226.635) ; v1(39,111.58) v1(39,218.635) ; v1(42,111.58) v1(42,210.635) ; v1(46,111.58) v1(46,202.635)
T/R: SOM1.JX2-64 U22.2 U22.4 | length 119.3
  Top Layer w0.203: SOM1.JX2-64@155.8,34.6 155.8,33.394 156.015,33.394 160.665,28.743 190.115,28.743 193.33,25.528 201.271,25.528 205.271,29.528 v1(246.263,29.528) ; v1(247,19) 249.525,16.475 U22.4@253.095,16.475 253.095,15.79 253.885,15 255.099,15 255.437,15.337 255.437,16.277 U22.2@255.635,16.475
  Bottom Layer w0.203: v1(246.263,29.528) 247,28.791 v1(247,19)
TX_CHN_1: SOM1.JX1-67 U10.7 | length 69.3
  Top Layer w0.203: U10.7@104.975,109.13 104.975,108.087 105.482,107.579 v1(105.482,106.321) ; v1@105.656,98.472 109.127,98.472 112.702,94.897 146.945,94.897 157.185,84.657 157.4,84.657 SOM1.JX1-67@157.4,83.45
  Bottom Layer w0.203: 105.482,98.679 v1(105.482,106.321)
  other v1: 105.69,98.472
TX_CHN_2: SOM1.JX2-32 U15.4 | length 178.4
  Top Layer w0.203: SOM1.JX2-32@143,34.6 143,33.394 143.215,33.394 153.455,23.153 187.799,23.153 191.015,19.938 203.587,19.938 207.587,23.938 v1(227.518,23.938) ; v1(227.518,107.006) 227.518,107.579 228.025,108.087 U15.4@228.025,109.13
  Bottom Layer w0.279: v1(227.518,23.938) v1(227.518,107.006)
TX_CHN_3: SOM1.JX2-61 U22.3 | length 130.5
  Top Layer w0.203: SOM1.JX2-61@155,39 155,40.207 155.009,40.207 160.218,45.416 v1(247.813,45.416) ; v1(248.545,18.951) 253.049,18.951 254.235,17.765 254.235,16.605 U22.3@254.365,16.475
  Bottom Layer w0.203: v1(247.813,45.416) 248.545,44.683 v1(248.545,18.951)
TXD_CHN_1: SOM1.JX2-2 U23.1 | length 216.9
  Top Layer w0.203: SOM1.JX2-2@131,34.6 131.266,34.334 131.266,33.468 132.935,31.8 136,31.8 150.448,17.352 v1(156.095,17.352) ; v1(156.095,198) U23.1@156.095,201.53
  Bottom Layer w0.203: v1(156.095,17.352) v1(156.095,198)
TXD_CHN_2: SOM1.JX2-1 U24.1 | length 171.4
  Top Layer w0.203: SOM1.JX2-1@131,39 131.266,39.266 131.266,40.132 132.935,41.8 136,41.8 v1(148.095,53.895) ; v1(148.095,198) U24.1@148.095,201.53
  Bottom Layer w0.203: v1(148.095,53.895) v1(148.095,198)
UART_Rx1: CN7.2 CN12.2 U28.16 | length 84.3
  Top Layer w0.203: CN7.2@360,7.375 v1(360,10) ; U28.16@370.425,62.25 372.75,62.25 v1(373,62)
  Bottom Layer w0.203: v1(360,10) 360.755,10.755 360.755,17.413 370,26.658 370,60 372,62 v1(373,62) 393.92,62 CN12.2@394,61.92
UART_Rx2: CN10.2 CN12.4 U28.26 | length 53.2
  Top Layer w0.203: U28.26@376.75,60.425 376.75,59.459 377.709,58.5 387.207,58.5 391.657,62.95 393.95,62.95 395,64 395,64.004 395.03,64.034 395.03,65.97 CN12.4@394,67 ; v1(390,48) 390,46 391,45 CN10.2@393.625,45
  Bottom Layer w0.203: v1(390,48) 390,51 395.426,56.426 395.426,65.574 CN12.4@394,67
UART_Rx3: CN8.2 CN12.6 U28.38 | length 101.4
  Top Layer w0.203: CN8.2@375,7.375 375,10 v1(376,11) ; U28.38@381.575,64.75 383.75,64.75 388,69 392,69 392.97,68.03 394,68.03 395.03,69.059 395.03,70.97 394,72 CN12.6@394,72.08 ; v1(387.501,50.537) 387.537,50.537 390.455,53.455 v1(393.836,53.455)
  Bottom Layer w0.203: v1(376,11) 378.545,11 387.501,19.956 v1(387.501,50.537) ; v1(393.836,53.455) 395.336,53.455 398.595,56.713 398.595,67.463 397.647,68.411 395.668,68.411 395.122,68.958 395.11,68.971 395.103,68.982 395.103,70.897 395.044,70.956 394,72 CN12.6@394,72.08
UART_Rx4: CN11.2 CN12.11 U28.48 | length 71.4
  Top Layer w0.203: U28.48@381.575,69.75 v1(383.495,69.75) ; CN11.2@393.625,30 390.953,30 388.175,32.779 388.175,49.921 391.04,52.786 395.54,52.786 399.212,56.457 399.212,67.788 397.595,69.405 396.675,69.405 CN12.11@396.54,69.54
  Bottom Layer w0.203: v1(383.495,69.75) 387.175,73.43 394.433,73.43 395.493,72.37 395.493,70.587 CN12.11@396.54,69.54
UART_Tx1: CN7.3 CN12.1 U28.17 | length 80.6
  Top Layer w0.203: v1(361.22,10) 361.22,7.405 CN7.3@361.25,7.375 ; v1(372.25,58.505) U28.17@372.25,60.425
  Bottom Layer w0.203: v1(361.22,10) 361.22,17.22 370.465,26.465 370.465,57.465 371.505,58.505 v1(372.25,58.505) 372.755,58 390.7,58 392.08,59.38 CN12.1@394,59.38
UART_Tx2: CN10.3 CN12.3 U28.27 | length 45.1
  Top Layer w0.203: U28.27@377.25,60.425 377.25,59.498 377.748,59 387,59 392.46,64.46 CN12.3@394,64.46 ; v1(391.182,46.25) CN10.3@393.625,46.25
  Bottom Layer w0.203: v1(391.182,46.25) 389.75,46.25 389.397,46.603 389.397,51.143 391.254,53 395.035,56.781 395.035,63.425 CN12.3@394,64.46
UART_Tx3: CN8.3 CN12.5 U28.39 | length 100.3
  Top Layer w0.203: v1(375,12) 373,10 373,6.68 373.68,6 376,6 376.25,6.25 CN8.3@376.25,7.375 ; U28.39@381.575,65.25 383.25,65.25 387.54,69.54 CN12.5@394,69.54 ; v1(386.56,50) 386.56,51.56 389,54 v1(395,54)
  Bottom Layer w0.203: v1(375,12) 377.418,12 386.56,21.141 v1(386.56,50) ; CN12.5@394,69.54 395.51,68.03 397.489,68.03 398.213,67.306 398.213,56.871 395.342,54 v1(395,54)
UART_Tx4: CN11.3 CN12.12 U28.52 | length 75
  Top Layer w0.203: U28.52@378.25,71.575 v1(378.25,73.495) ; CN11.3@393.625,31.25 390.449,31.25 388.702,32.997 388.702,49.702 391.405,52.405 395.698,52.405 399.593,56.3 399.593,70.407 398,72 396.62,72 CN12.12@396.54,72.08
  Bottom Layer w0.203: v1(378.25,73.495) 378.755,74 394.62,74 CN12.12@396.54,72.08
USB_1.8V: C37.1 C38.1 C49.1 C50.1 C51.1 TP7.1 U28.12 U28.37 U28.49 U28.64 | length 64.5
  Top Layer w0.203: C51.1@355,77.85 C50.1@360.85,77.85 ; C49.1@367,77.85 C50.1@360.85,77.85 ; U28.12@370.425,64.25 v1(372.345,64.25) ; v1(372.25,69.655) U28.64@372.25,71.575 372.25,71.88 372.205,71.925 C37.1@359,71.925 359,76 C50.1@360.85,77.85 ; U28.49@379.75,71.575 380.077,71.248 v1(380.077,69.588) ; v1(380.001,64.636) 380.407,64.636 380.722,64.32 381.505,64.32 U28.37@381.575,64.25 383.75,64.25 385,63 386.064,63 TP7.1@387,63.936
  FlatSat VCC w0.203: v1@372.283,69.622 v1@380.043,69.622 ; v1@372.297,64.298 v1@372.297,69.608 ; v1@380.039,64.674 v1@380.039,69.617
  Bottom Layer w0.203: v1(372.25,69.655) v1@372.297,69.608 ; v1@372.297,64.298 v1(372.345,64.25) ; v1(380.001,64.636) v1@380.039,64.674 ; v1@380.039,69.617 v1@380.043,69.622
USB_3.3V: C36.1 C42.1 C43.1 C44.1 C45.1 C47.1 FB1.1 FB3.1 R22.2 R24.2 TP5.1 U28.20 U28.31 U28.42 U28.50 U28.56 U29.5 | length 52.6
  Top Layer w0.203: v1(359,63.036) FB3.1@359,64.111 ; U28.20@373.75,60.425 373.75,61.874 v1(374.464,62.588) ; C36.1@373.925,83.075 373.925,83 374,83.075 v1(375,83.075) ; R24.2@374.619,76.585 v1(374.619,77.66) ; v1(374.95,86.725) U29.5@374.95,87.8 ; R22.2@376.016,55 378.925,55 C45.1@379,54.925 ; v1(376.25,70.5) U28.56@376.25,71.575 U28.56@376.269,71.556 ; v1(379,50) 379,48.925 384,48.925 385.925,48.925 387,47.85 387,41 385,39 TP5.1@381,39 ; C45.1@379,54.85 C45.1@379,54.925 ; v1(379,56) C45.1@379,54.925 ; v1(379,63) 379.25,62.75 U28.31@379.25,60.425 U28.31@379.231,60.444 ; v1(379,67) 379.25,66.75 U28.42@381.538,66.75 ; v1(379.25,70.5) U28.50@379.25,71.575 379.25,73.394 379,73.644 FB1.1@379,75.111 379.111,75 C47.1@381.075,75 ; U28.42@381.519,66.769 U28.42@381.538,66.75 ; U28.42@381.556,66.731 U28.42@381.538,66.75 ; U28.42@381.575,66.75 U28.42@381.538,66.75 ; C44.1@384,54.85 379.075,54.85 C45.1@379,54.925
USB_5V: C32.1 C33.1 C46.1 FB2.2 TP8.1 U29.1 U29.3 | length 43.8
  Top Layer w0.203: C33.1@369.925,95 371,95 372.925,96.925 372.925,98.925 C32.1@372.85,99 374,99 375.925,97.075 375.925,91.4 374.95,90.425 U29.1@374.95,90.2 ; U29.3@373.05,90.2 373.05,89.45 373.5,89 374.5,89 374.95,89.45 U29.1@374.95,90.2 ; TP8.1@389,93 FB2.2@389,85.889 383.111,85.889 378.8,90.2 U29.1@374.95,90.2
USB_RX_N: R18.2 U28.7 | length 55.3
  Top Layer w0.203: U28.7@370.425,66.75 370.406,66.731 369.663,66.731 369.635,66.703 366.742,66.703 365.366,65.327 365.366,63.497 366.316,62.546 366.316,56.891 364.594,55.168 364.594,39.406 377.797,26.203 377.797,23.245 377.678,23.126 377.237,23.126 R18.2@377,22.889
USB_RX_P: R20.2 U28.8 | length 54.6
  Top Layer w0.203: U28.8@370.425,66.25 370.406,66.269 369.663,66.269 369.635,66.297 366.911,66.297 365.772,65.158 365.772,63.665 366.722,62.715 366.722,56.722 365,55 365,39.575 378.203,26.372 378.203,23.245 378.322,23.126 378.763,23.126 R20.2@379,22.889
USB_SHIELD: CN9.0 R21.2 | length 26.5
  Top Layer w0.203: R21.2@389,18.016 389.016,18 391,18 392,17 392,16 392.8,15.2 CN9.0@394,15.2
  Top Layer w0.381: CN9.0@396.7,9.2 CN9.0@396.7,11.7 ; CN9.0@396.7,13.7 CN9.0@396.7,16.2
  FlatSat GND w0.381: CN9.0@394,10.2 394,10.05 394.85,9.2 CN9.0@396.7,9.2 396.91,9.2 397.149,9.44 397.149,9.649 398,10.5 398,14.9 397.149,15.751 397.149,15.96 396.91,16.2 CN9.0@396.7,16.2 394.85,16.2 394,15.35 CN9.0@394,15.2
USB_TX_N: CN9.2 R18.1 | length 21.7
  Top Layer w0.203: R18.1@377,21.111 377.237,20.874 377.678,20.874 377.797,20.755 377.797,19.203 384.287,12.713 389.713,12.713 390.253,12.172 393.308,12.172 393.331,12.148 393.902,12.148 CN9.2@394,12.05 CN9.2@393.939,11.989
USB_TX_P: CN9.3 R20.1 | length 21
  Top Layer w0.203: R20.1@379,21.111 378.763,20.874 378.322,20.874 378.203,20.755 378.203,19.372 384.456,13.119 389.881,13.119 390.422,12.578 393.308,12.578 393.331,12.602 393.902,12.602 CN9.3@394,12.7
V1_E: CN2.1 J8.1 J8.3 J8.5 J8.7 J8.9 J8.11 J8.13 TP12.1 | length 60.3
  Top Layer w0.203: J8.1@214.699,9.07 214.699,10.699 218,14 TP12.1@222,14
  FlatSat VCC w0.762: CN2.1@168.475,8 172.475,4 194,4 197,7 197.389,7 J8.13@199.459,9.07 J8.11@201.999,9.07 J8.9@204.539,9.07 J8.7@207.079,9.07 J8.5@209.619,9.07 J8.3@212.159,9.07 J8.1@214.699,9.07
